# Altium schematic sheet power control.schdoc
size 261 x 179 mm
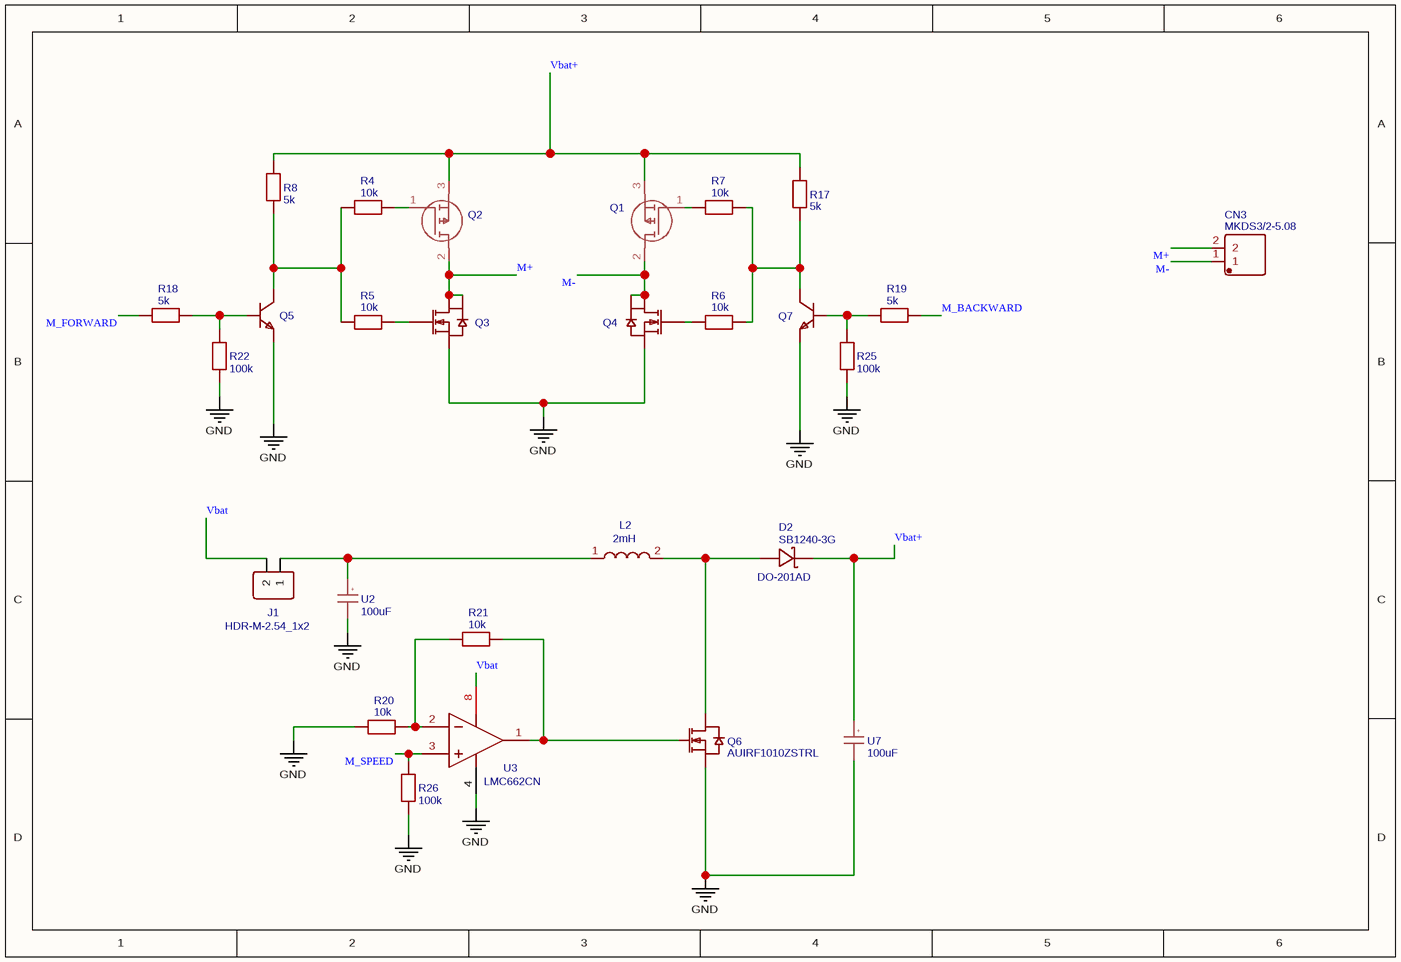
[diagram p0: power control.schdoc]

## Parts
CN3  MKDS3/2-5.08  [CONN-TH_MKDS3-2-5.08]
D2  SB1240-3G  [DO-201AD]
J1  HDR-M-2.54_1x2  [HDR-M-2.54_1X2]
L2  2mH  [DENO230001]
Q1  TSM7P06CP_ROG  [TSM7P06CPROG]  (value not drawn)
Q2  TSM7P06CP_ROG  [TSM7P06CPROG]  (value not drawn)
Q3  TSM950N10CW RPG  [SOT-223-3_L6.7-W3.7-P2.30-LS7.0-BR]  (value not drawn)
Q4  TSM950N10CW RPG  [SOT-223-3_L6.7-W3.7-P2.30-LS7.0-BR]  (value not drawn)
Q5  NSS40201LT1G  [SOT-23-3_L2.9-W1.6-P1.90-LS2.8-BR]  (value not drawn)
Q6  AUIRF1010ZSTRL  [D2PAK_L10.0-W9.0-P2.54-LS15.0-BR]
Q7  NSS40201LT1G  [SOT-23-3_L2.9-W1.6-P1.90-LS2.8-BR]  (value not drawn)
R4  10k  [R0805]
R5  10k  [R0805]
R6  10k  [R0805]
R7  10k  [R0805]
R8  5k  [R0805]
R17  5k  [R0805]
R18  5k  [R0805]
R19  5k  [R0805]
R20  10k  [R0805]
R21  10k  [R0805]
R22  100k  [R0805]
R25  100k  [R0805]
R26  100k  [R0805]
U2  100uF  [WCAP-PTG5_8X11.5(DXL)]
U3  LMC662CN  [PDIP-8_L9.3-W6.4-P2.54-LS7.6-BL]
U7  100uF  [WCAP-PTG5_8X11.5(DXL)]

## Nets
GND: Q3.3(S) Q4.3(S) Q5.2(E) Q6.3(S) Q7.2(E) R20.1 R22.1 R25.1 R26.1 U2.2(-) U3.4(V-) U7.2(-)
M+: CN3.2 Q2.2(D) Q3.2(D) Q3.4(D)
M-: CN3.1 Q1.2(D) Q4.2(D) Q4.4(D)
M_BACKWARD: R19.2
M_FORWARD: R18.1
M_SPEED: R26.2 U3.3(IN_A+)
Vbat: J1.2 U3.8(V+)
Vbat+: D2.2(K) Q1.3(S) Q2.3(S) R8.2 R17.2 U7.1(+)
NetD2_1: D2.1(A) L2.2 Q6.2(D)
NetJ1_1: J1.1 L2.1 U2.1(+)
NetQ1_1: Q1.1(G) R7.1
NetQ2_1: Q2.1(G) R4.2
NetQ3_1: Q3.1(G) R5.2
NetQ4_1: Q4.1(G) R6.1
NetQ5_1: Q5.1(B) R18.2 R22.2
NetQ5_3: Q5.3(C) R4.1 R5.1 R8.1
NetQ6_1: Q6.1(G) R21.2 U3.1(OUT_A)
NetQ7_1: Q7.1(B) R19.1 R25.2
NetQ7_3: Q7.3(C) R6.2 R7.2 R17.1
NetR20_2: R20.2 R21.1 U3.2(IN_A-)

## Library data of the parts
CN3 = MKDS3/2-5.08: Manufacturer: Phoenix Contact(菲尼克斯); Manufacturer Part: 1711725
D2 = SB1240-3G: Manufacturer: MDD; Contributor: ankur.korat123; Package Display: Yes
J1 = HDR-M-2.54_1x2: Contributor: LCEDA_Lib
L2 = 2mH: Manufacturer Part: DENO-23-0001; Contributor: jorge.martinezt; Package Display: No
Q1 Q2 = TSM7P06CP_ROG: Contributor: andreafato
Q3 Q4 = TSM950N10CW RPG: Manufacturer: Taiwan Semiconductor(台湾半导体); Contributor: lcsc
Q5 Q7 = NSS40201LT1G: Manufacturer: onsemi(安森美); Contributor: LCSC
Q6 = AUIRF1010ZSTRL: Manufacturer: Infineon(英飞凌); Contributor: LCSC
R4-R7 R20 R21 = 10k: nameAlias: Value(Ω); Contributor: LCEDA_Lib
R8 R17-R19 = 5k: nameAlias: Value(Ω); Contributor: LCEDA_Lib
R22 R25 R26 = 100k: nameAlias: Value(Ω); Contributor: LCEDA_Lib
U2 U7 = 100uF: Manufacturer Part: 870025574005; Contributor: nexuspiotrmalek; Package Display: No
U3 = LMC662CN: subpart_no: 1; Manufacturer: TI(德州仪器)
